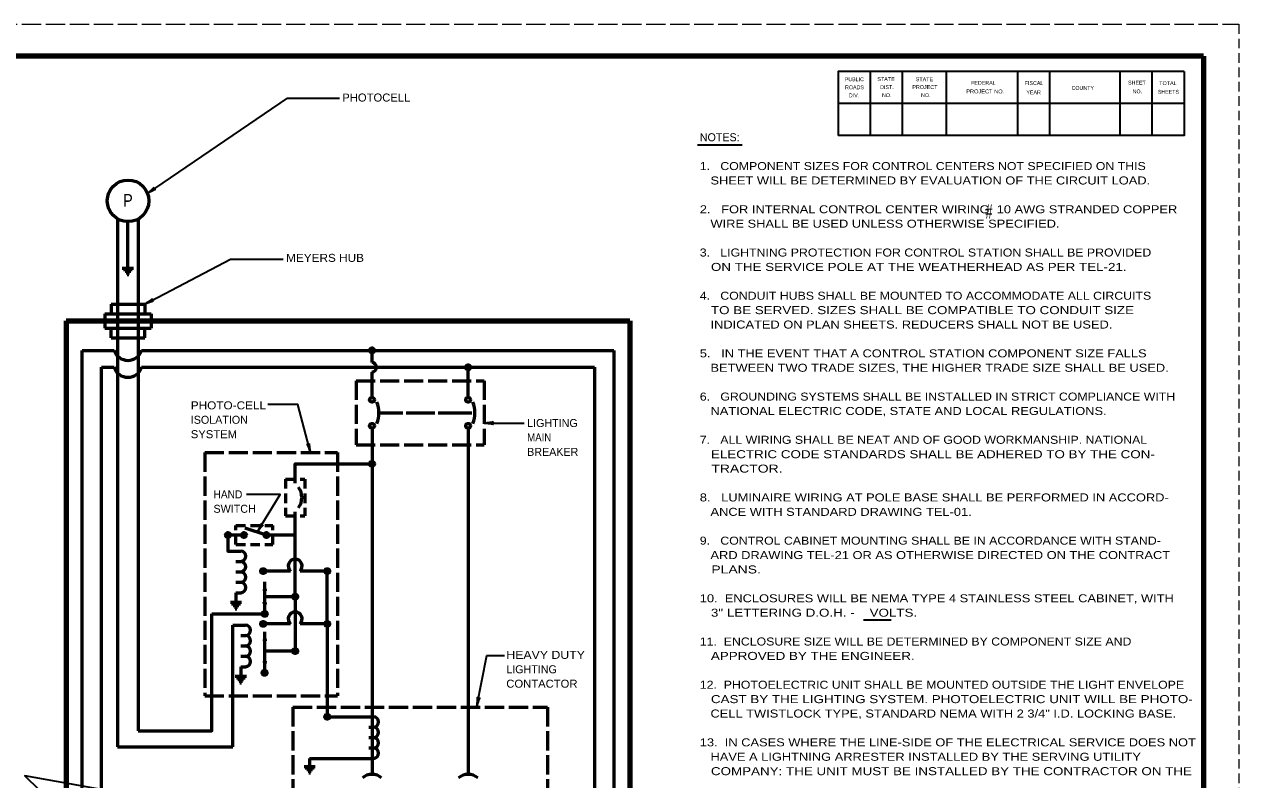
# Model space of a CAD drawing. Extents: x -1 to 679, y 0 to 440.
# Drawn here: x 299.3 to 678.6, y 203.7 to 439.6 of the extents above; entities that cross this region are included whole.
import ezdxf

# ---------------------------------------------------------------- set-up
doc = ezdxf.new("R2010")
doc.units = 0
doc.linetypes.add('LONG_DASHED', pattern=[7.5, 6, -1.5])
doc.linetypes.add('MEDIUM_DASHED', pattern=[4.5, 3, -1.5])
doc.layers.add('1', color=7, linetype='Continuous', lineweight=53)
doc.layers.add('61', color=7, linetype='Continuous', lineweight=35)

msp = doc.modelspace()

# ---------------------------------------------------------------- hatches: boundary and pattern name
at = {"layer": '1'}
for points in [[(408.688, 337.772, 1), (407.188, 337.772, 1)], [(438.688, 332.488, 1), (437.188, 332.488, 1)], [(408.688, 302.339, 1), (407.188, 302.339, 1)], [(363.688, 280.089, 1), (362.188, 280.089, 1)], [(368.688, 280.089, 1), (367.188, 280.089, 1)], [(375.688, 280.089, 1), (374.188, 280.089, 1)], [(374.688, 268.839, 1), (373.188, 268.839, 1)], [(394.688, 268.839, 1), (393.188, 268.839, 1)], [(384.688, 260.839, 1), (383.188, 260.839, 1)], [(375.188, 255.464, 1), (373.688, 255.464, 1)], [(374.688, 252.339, 1), (373.188, 252.339, 1)], [(394.688, 252.339, 1), (393.188, 252.339, 1)], [(384.688, 243.839, 1), (383.188, 243.839, 1)], [(375.118, 237.068, 1), (373.618, 237.068, 1)], [(394.688, 223.339, 1), (393.188, 223.339, 1)]]:
    msp.add_hatch(color=256, dxfattribs=at).paths.add_polyline_path(points)

# ---------------------------------------------------------------- linework, layer by layer
at = {"layer": '1', "linetype": 'MEDIUM_DASHED', "lineweight": 13}
msp.add_line((678.59, 439.624), (678.57, -0.396), dxfattribs=at)
at = {"layer": '1', "lineweight": 35}
for p, q in [((509.579, 402.02), (523.484, 402.02)), ((442.938, 315.072), (455.396, 315.072)), ((561.455, 253.56), (570.081, 253.56))]:
    msp.add_line(p, q, dxfattribs=at)
at = {"layer": '1'}
for p, q in [((328.438, 378.884), (328.438, 213.964)), ((331.688, 363.481), (331.688, 377.981)), ((334.938, 378.819), (334.938, 218.964)), ((329.938, 363.481), (333.438, 363.481)), ((330.313, 362.981), (333.063, 362.981)), ((330.813, 362.481), (332.563, 362.481)), ((331.188, 361.981), (332.188, 361.981)), ((331.438, 361.481), (331.938, 361.481)), ((324.438, 349.214), (338.938, 349.214)), ((324.438, 349.214), (324.438, 344.714)), ((326.438, 352.214), (336.938, 352.214)), ((326.438, 352.214), (326.438, 349.214)), ((336.938, 352.214), (336.938, 349.214)), ((338.938, 349.214), (338.938, 344.714)), ((324.438, 344.714), (338.938, 344.714)), ((326.438, 341.714), (326.438, 344.714)), ((326.438, 341.714), (336.938, 341.714)), ((336.938, 341.714), (336.938, 344.714)), ((317.438, 337.772), (327.438, 337.772)), ((317.438, 183.839), (317.438, 337.772)), ((335.938, 337.772), (483.438, 337.772)), ((407.938, 333.988), (407.938, 337.772)), ((483.438, 337.772), (483.438, 138.464)), ((323.438, 332.488), (327.438, 332.488)), ((323.438, 183.839), (323.438, 332.488)), ((335.938, 332.488), (477.438, 332.488)), ((407.938, 323.089), (407.938, 330.988)), ((437.938, 323.089), (437.938, 332.488)), ((477.438, 332.488), (477.438, 138.464)), ((410.059, 318.277), (417.559, 318.277)), ((418.559, 318.277), (427.559, 318.277)), ((428.559, 318.277), (439.059, 318.277)), ((407.938, 313.464), (407.938, 205.339)), ((437.938, 313.464), (437.938, 205.339)), ((383.938, 260.839), (383.938, 287.339)), ((374.938, 280.089), (368.28, 282.253)), ((367.938, 280.089), (362.938, 280.089)), ((383.938, 280.089), (374.938, 280.089)), ((365.438, 271.839), (366.938, 271.839)), ((365.438, 268.589), (366.938, 268.589)), ((382.438, 268.839), (373.938, 268.839)), ((365.438, 265.339), (366.938, 265.339)), ((365.438, 262.089), (366.938, 262.089)), ((365.438, 262.089), (365.438, 259.089)), ((374.438, 256.214), (374.438, 265.464)), ((363.688, 259.089), (367.188, 259.089)), ((364.063, 258.589), (366.813, 258.589)), ((364.563, 258.089), (366.313, 258.089)), ((383.938, 260.839), (374.438, 260.839)), ((357.938, 255.464), (374.438, 255.464)), ((364.938, 257.589), (365.938, 257.589)), ((365.188, 257.089), (365.688, 257.089)), ((364.438, 213.964), (364.438, 251.964)), ((364.438, 251.964), (368.438, 251.964)), ((382.438, 252.339), (373.938, 252.339)), ((393.938, 252.339), (385.438, 252.339)), ((366.938, 248.714), (368.438, 248.714)), ((374.438, 237.839), (374.438, 249.839)), ((366.938, 245.464), (368.438, 245.464)), ((366.938, 242.214), (368.438, 242.214)), ((366.938, 238.964), (368.438, 238.964)), ((366.938, 238.964), (366.938, 235.964)), ((365.188, 235.964), (368.688, 235.964)), ((365.563, 235.464), (368.313, 235.464)), ((366.063, 234.964), (367.813, 234.964)), ((366.438, 234.464), (367.438, 234.464)), ((366.688, 233.964), (367.188, 233.964)), ((406.938, 220.089), (408.438, 220.089)), ((407.938, 223.339), (408.438, 223.339)), ((406.938, 216.839), (408.438, 216.839)), ((328.438, 213.964), (364.438, 213.964)), ((406.938, 213.589), (408.438, 213.589)), ((388.438, 210.339), (408.438, 210.339)), ((388.438, 210.339), (388.438, 207.839)), ((386.688, 207.839), (390.188, 207.839)), ((387.063, 207.339), (389.813, 207.339)), ((387.563, 206.839), (389.313, 206.839)), ((387.938, 206.339), (388.938, 206.339)), ((388.188, 205.839), (388.688, 205.839))]:
    msp.add_line(p, q, dxfattribs=at)
at = {"layer": '1', "lineweight": 140}
for p, q in [((312.438, 346.964), (312.438, 144.964)), ((312.438, 346.964), (488.438, 346.964)), ((488.438, 346.964), (488.438, 144.964))]:
    msp.add_line(p, q, dxfattribs=at)
at = {"layer": '1', "linetype": 'LONG_DASHED'}
for p, q in [((402.938, 328.277), (442.938, 328.277)), ((402.938, 328.277), (402.938, 308.277)), ((442.938, 328.277), (442.938, 308.277)), ((402.938, 308.277), (442.938, 308.277)), ((355.688, 305.839), (397.188, 305.839)), ((355.688, 305.839), (355.688, 229.839)), ((397.188, 305.839), (397.188, 229.839)), ((355.688, 229.839), (397.188, 229.839)), ((383.188, 226.339), (462.688, 226.339)), ((383.188, 226.339), (383.188, 196.339)), ((462.688, 226.339), (462.688, 196.339))]:
    msp.add_line(p, q, dxfattribs=at)
at = {"layer": '1', "linetype": 'MEDIUM_DASHED'}
for p, q in [((380.938, 297.589), (386.938, 297.589)), ((380.938, 297.589), (380.938, 286.089)), ((386.938, 297.589), (386.938, 286.089)), ((380.938, 286.089), (386.938, 286.089)), ((365.438, 277.089), (365.438, 283.089)), ((365.438, 283.089), (376.938, 283.089)), ((376.938, 277.089), (376.938, 283.089)), ((365.438, 277.089), (376.938, 277.089))]:
    msp.add_line(p, q, dxfattribs=at)
at = {"layer": '1', "lineweight": 35}
for points in [[(337.808, 386.821), (381.523, 416.518), (397.724, 416.518)], [(336.938, 352.214), (363.703, 366.281), (380.227, 366.281)], [(388.693, 305.839), (384.763, 320.906), (375.367, 320.906)], [(372.108, 281.009), (379.255, 292.709), (368.677, 292.709)], [(440.662, 226.628), (443.823, 242.437), (449.331, 242.437)], [(403.002, 186.37), (299.492, 204.881), (321.528, 183.359)]]:
    msp.add_lwpolyline(points, dxfattribs=at)
at = {"layer": '1'}
for points in [[(383.938, 296.339), (383.938, 302.339), (407.938, 302.339)], [(362.938, 280.089), (362.938, 275.089), (366.938, 275.089)], [(393.938, 252.339), (393.938, 268.839), (385.438, 268.839)], [(383.938, 260.839), (383.938, 243.839), (374.438, 243.839)], [(334.938, 218.964), (357.938, 218.964), (357.938, 255.464)], [(393.938, 252.339), (393.938, 223.339), (407.938, 223.339)]]:
    msp.add_lwpolyline(points, dxfattribs=at)
for centre, radius in [((331.744, 384.481), 6.5), ((407.938, 337.772), 0.75), ((437.938, 332.488), 0.75), ((407.938, 322.339), 0.75), ((437.938, 322.339), 0.75), ((407.938, 314.214), 0.75), ((437.938, 314.214), 0.75), ((407.938, 302.339), 0.75), ((362.938, 280.089), 0.75), ((367.938, 280.089), 0.75), ((374.938, 280.089), 0.75), ((373.938, 268.839), 0.75), ((393.938, 268.839), 0.75), ((383.938, 260.839), 0.75), ((374.438, 255.464), 0.75), ((373.938, 252.339), 0.75), ((393.938, 252.339), 0.75), ((383.938, 243.839), 0.75), ((374.368, 237.068), 0.75), ((393.938, 223.339), 0.75)]:
    msp.add_circle(centre, radius, dxfattribs=at)
for centre, radius, start, end in [((331.688, 339.093), 4.45, 197.26122, 342.73878), ((407.814, 332.488), 1.505, 274.71933, 85.28067), ((331.688, 333.808), 4.45, 197.26122, 342.73878), ((400.923, 318.277), 9.136, 338.74274, 21.25726), ((430.923, 318.277), 9.136, 338.74274, 21.25726), ((380.601, 291.839), 5.419, 323.14889, 36.85111), ((366.868, 273.464), 1.627, 272.45324, 87.54675), ((366.868, 270.214), 1.627, 272.45324, 87.54675), ((383.938, 270.408), 2.17, 313.71808, 226.28192), ((366.868, 266.964), 1.627, 272.45324, 87.54675), ((366.868, 263.714), 1.627, 272.45324, 87.54675), ((383.938, 253.908), 2.17, 313.71808, 226.28192), ((368.368, 250.339), 1.627, 272.45324, 87.54675), ((368.368, 247.089), 1.627, 272.45324, 87.54675), ((368.368, 243.839), 1.627, 272.45324, 87.54675), ((368.368, 240.589), 1.627, 272.45324, 87.54675), ((408.368, 221.714), 1.627, 272.45324, 87.54675), ((408.368, 218.464), 1.627, 272.45324, 87.54675), ((408.368, 215.214), 1.627, 272.45324, 87.54675), ((408.368, 211.964), 1.627, 272.45324, 87.54675), ((407.938, 200.777), 4.562, 48.88791, 131.11209), ((437.938, 200.777), 4.562, 48.88791, 131.11209)]:
    msp.add_arc(centre, radius, start, end, dxfattribs=at)
at = {"layer": '1', "lineweight": 40}
for centre, major_axis, ratio, start_param, end_param in [((338.555, 387.663), (-1.389, -1.133), 0.122415, 0.8963533, 3.1415927), ((338.854, 387.276), (1.552, 0.842), 0.07063, 6.2823074, 8.5597026), ((337.775, 352.967), (-1.508, -0.969), 0.122415, 0.8963533, 3.1415927), ((337.775, 352.967), (-1.508, -0.969), 0.122415, 0.8963533, 3.1415927), ((338.028, 352.548), (-1.637, -0.662), 0.07063, 3.1407148, 5.41811), ((338.028, 352.548), (-1.637, -0.662), 0.07063, 3.1407148, 5.41811), ((444.058, 314.861), (-1.756, 0.176), 0.07063, 3.1407148, 5.41811), ((444.058, 314.861), (-1.756, 0.176), 0.07063, 3.1407148, 5.41811), ((444.029, 315.349), (-1.786, -0.156), 0.122415, 0.8963533, 3.1415927), ((444.029, 315.349), (-1.786, -0.156), 0.122415, 0.8963533, 3.1415927), ((388.15, 306.826), (0.602, -1.689), 0.122415, 0.8963533, 3.1415927), ((388.15, 306.826), (0.602, -1.689), 0.122415, 0.8963533, 3.1415927), ((388.615, 306.977), (0.273, -1.744), 0.07063, 3.1407148, 5.41811), ((388.615, 306.977), (0.273, -1.744), 0.07063, 3.1407148, 5.41811), ((372.441, 282.084), (-0.798, -1.605), 0.122415, 0.8963533, 3.1415927), ((372.441, 282.084), (-0.798, -1.605), 0.122415, 0.8963533, 3.1415927), ((372.872, 281.855), (1.066, 1.407), 0.07063, 6.2823074, 8.5597026), ((372.872, 281.855), (1.066, 1.407), 0.07063, 6.2823074, 8.5597026), ((374.226, 264.344), (0.176, 1.756), 0.07063, 3.1407148, 5.41811), ((374.714, 264.373), (-0.156, 1.786), 0.122415, 0.8963533, 3.1415927), ((374.161, 257.306), (0.156, -1.786), 0.122415, 0.8963533, 3.1415927), ((374.649, 257.335), (-0.176, -1.756), 0.07063, 3.1407148, 5.41811), ((374.226, 248.719), (0.176, 1.756), 0.07063, 3.1407148, 5.41811), ((374.714, 248.748), (-0.156, 1.786), 0.122415, 0.8963533, 3.1415927), ((374.161, 238.931), (0.156, -1.786), 0.122415, 0.8963533, 3.1415927), ((374.649, 238.96), (-0.176, -1.756), 0.07063, 3.1407148, 5.41811), ((440.605, 227.752), (-0.197, -1.782), 0.122415, 0.8963533, 3.1415927), ((441.089, 227.685), (0.517, 1.688), 0.07063, 6.2823074, 8.5597026)]:
    msp.add_ellipse(centre, major_axis=major_axis, ratio=ratio, start_param=start_param, end_param=end_param, dxfattribs=at)
at = {"layer": '61', "linetype": 'LONG_DASHED', "lineweight": 13}
msp.add_line((-1.43, 439.624), (678.59, 439.624), dxfattribs=at)
at = {"layer": '61', "lineweight": 158}
msp.add_line((667.61, 429.624), (667.63, 9.584), dxfattribs=at)
at = {"layer": '61'}
for p, q in [((563.53, 424.864), (563.53, 404.864)), ((573.53, 424.864), (573.53, 404.864)), ((587.21, 424.864), (587.21, 404.864)), ((609.53, 424.864), (609.53, 404.864)), ((619.53, 424.864), (619.53, 404.864)), ((641.51, 424.884), (641.51, 404.884)), ((651.51, 424.884), (651.51, 404.884)), ((661.53, 414.844), (553.51, 414.864))]:
    msp.add_line(p, q, dxfattribs=at)
at = {"layer": '61', "lineweight": 158}
msp.add_lwpolyline([(667.61, 429.624), (28.57, 429.624), (28.57, 9.604)], dxfattribs=at)
at = {"layer": '61'}
for points in [[(661.51, 424.884), (553.53, 424.864), (553.53, 404.864)], [(661.51, 424.884), (661.51, 404.884), (553.53, 404.864)]]:
    msp.add_lwpolyline(points, dxfattribs=at)

# ---------------------------------------------------------------- texts
at = {"layer": '1'}
for s, height, width, p in [('PHOTOCELL', 2.5, 1.05, (398.634, 415.491)), ('1.   COMPONENT SIZES FOR CONTROL CENTERS NOT SPECIFIED ON THIS', 2.5, 1.15, (510.287, 394.089)), ('   SHEET WILL BE DETERMINED BY EVALUATION OF THE CIRCUIT LOAD.', 2.5, 1.2, (510.287, 389.589)), ('P', 4, 0.85, (330.169, 382.608)), ('2.   FOR INTERNAL CONTROL CENTER WIRING  10 AWG STRANDED COPPER', 2.5, 1.2, (510.287, 380.589)), ('#', 4.5, 0.65, (599.527, 378.905)), ('   WIRE SHALL BE USED UNLESS OTHERWISE SPECIFIED.', 2.5, 1.2, (510.287, 376.089)), ('MEYERS HUB', 2.5, 1.1, (381.094, 365.415)), ('3.   LIGHTNING PROTECTION FOR CONTROL STATION SHALL BE PROVIDED', 2.5, 1.15, (510.287, 367.089)), ('   ON THE SERVICE POLE AT THE WEATHERHEAD AS PER TEL-21.', 2.5, 1.25, (510.287, 362.589)), ('4.   CONDUIT HUBS SHALL BE MOUNTED TO ACCOMMODATE ALL CIRCUITS', 2.5, 1.15, (510.287, 353.589)), ('   TO BE SERVED. SIZES SHALL BE COMPATIBLE TO CONDUIT SIZE ', 2.5, 1.25, (510.287, 349.089)), ('   INDICATED ON PLAN SHEETS. REDUCERS SHALL NOT BE USED.', 2.5, 1.2, (510.287, 344.589)), ('5.   IN THE EVENT THAT A CONTROL STATION COMPONENT SIZE FALLS', 2.5, 1.2, (510.287, 335.589)), ('   BETWEEN TWO TRADE SIZES, THE HIGHER TRADE SIZE SHALL BE USED.', 2.5, 1.2, (510.287, 331.089)), ('6.   GROUNDING SYSTEMS SHALL BE INSTALLED IN STRICT COMPLIANCE WITH', 2.5, 1.15, (510.287, 322.089)), ('PHOTO-CELL', 2.5, 1.1, (351.334, 319.345)), ('   NATIONAL ELECTRIC CODE, STATE AND LOCAL REGULATIONS.', 2.5, 1.2, (510.287, 317.589)), ('SYSTEM', 2.5, 1.05, (351.334, 310.345)), ('MAIN', 2.5, 0.9, (456.38, 309.325)), ('7.   ALL WIRING SHALL BE NEAT AND OF GOOD WORKMANSHIP. NATIONAL', 2.5, 1.15, (510.287, 308.589)), ('   ELECTRIC CODE STANDARDS SHALL BE ADHERED TO BY THE CON-', 2.5, 1.25, (510.287, 304.089)), ('   TRACTOR.', 2.5, 1.3, (510.287, 299.589)), ('HAND', 2.5, 0.95, (358.429, 291.547)), ('8.   LUMINAIRE WIRING AT POLE BASE SHALL BE PERFORMED IN ACCORD-', 2.5, 1.2, (510.287, 290.589)), ('   ANCE WITH STANDARD DRAWING TEL-01.', 2.5, 1.2, (510.287, 286.089)), ('9.   CONTROL CABINET MOUNTING SHALL BE IN ACCORDANCE WITH STAND-', 2.5, 1.15, (510.287, 277.089)), ('   ARD DRAWING TEL-21 OR AS OTHERWISE DIRECTED ON THE CONTRACT ', 2.5, 1.2, (510.287, 272.589)), ('   PLANS.', 2.5, 1.3, (510.287, 268.089)), ('10.  ENCLOSURES WILL BE NEMA TYPE 4 STAINLESS STEEL CABINET, WITH', 2.5, 1.2, (510.287, 259.089)), ('   3" LETTERING D.O.H. -    VOLTS.', 2.5, 1.25, (510.287, 254.589)), ('11.  ENCLOSURE SIZE WILL BE DETERMINED BY COMPONENT SIZE AND', 2.5, 1.15, (510.287, 245.589)), ('HEAVY DUTY', 2.5, 1.15, (449.862, 241.415)), ('   APPROVED BY THE ENGINEER.', 2.5, 1.25, (510.287, 241.089)), ('CONTACTOR', 2.5, 1.05, (449.862, 232.415)), ('12.  PHOTOELECTRIC UNIT SHALL BE MOUNTED OUTSIDE THE LIGHT ENVELOPE', 2.5, 1.15, (510.287, 232.089)), ('   CAST BY THE LIGHTING SYSTEM. PHOTOELECTRIC UNIT WILL BE PHOTO-', 2.5, 1.25, (510.287, 227.589)), ('   CELL TWISTLOCK TYPE, STANDARD NEMA WITH 2 3/4" I.D. LOCKING BASE.', 2.5, 1.2, (510.287, 223.089)), ('13.  IN CASES WHERE THE LINE-SIDE OF THE ELECTRICAL SERVICE DOES NOT', 2.5, 1.2, (510.287, 214.089)), ('   HAVE A LIGHTNING ARRESTER INSTALLED BY THE SERVING UTILITY', 2.5, 1.2, (510.287, 209.589)), ('   COMPANY: THE UNIT MUST BE INSTALLED BY THE CONTRACTOR ON THE', 2.5, 1.25, (510.287, 205.089))]:
    msp.add_text(s, height=height, dxfattribs=dict(at, width=width)).set_placement(p)
for s, p in [('NOTES:', (510.287, 403.089)), ('ISOLATION', (351.334, 314.845)), ('LIGHTING', (456.38, 313.825)), ('BREAKER', (456.38, 304.825)), ('SWITCH', (358.429, 287.047)), ('LIGHTING', (449.862, 236.915))]:
    msp.add_text(s, height=2.5, dxfattribs=at).set_placement(p)
at = {"layer": '61'}
for s, rotation, p in [('PUBLIC', 0.033, (555.57, 421.844)), ('FEDERAL', 0.007, (595.03, 420.724)), ('FISCAL', 359.942, (611.77, 420.664)), ('SHEET', 0.059, (644.03, 420.784)), ('ROADS', 0.124, (555.65, 419.324)), ('DIV.', 359.932, (556.85, 416.824)), ('DIST.', 0.056, (566.61, 419.404)), ('YEAR', 0.105, (612.29, 417.764)), ('COUNTY', 0.069, (626.39, 419.124)), ('SHEETS', 359.959, (653.31, 417.944))]:
    msp.add_text(s, height=1.201, rotation=rotation, dxfattribs=at).set_placement(p)
for s, rotation, width, p in [('STATE', 0.059, 1.05, (565.73, 421.904)), ('STATE', 0.059, 1.05, (577.73, 421.844)), ('TOTAL', 359.926, 1.05, (653.77, 420.644)), ('NO.', 359.852, 0.95, (567.19, 416.884)), ('PROJECT', 359.908, 1.05, (576.65, 419.424)), ('NO.', 0.225, 0.95, (579.39, 416.884)), ('PROJECT NO.', 359.922, 1.1, (593.49, 418.064)), ('NO.', 359.852, 0.95, (645.45, 418.064))]:
    msp.add_text(s, height=1.201, rotation=rotation, dxfattribs=dict(at, width=width)).set_placement(p)

doc.saveas('drawing.dxf')
